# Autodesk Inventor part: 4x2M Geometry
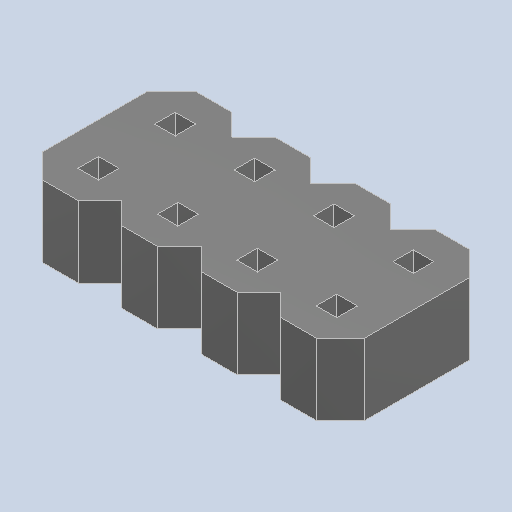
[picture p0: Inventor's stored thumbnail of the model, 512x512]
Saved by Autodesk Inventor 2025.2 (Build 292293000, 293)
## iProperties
Created: 2025-04
Part Number: 4x2M Geometry
Material: Generic
Description: PART-4x2M Geometry-DESC
Document SubType Name: Modeling
Designer: BennF
Density: 1 g/cm^3
Appearance: Default
Author: BennF
Revision Number: NONE
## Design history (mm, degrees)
feature "4x2"
body "Solid1"
